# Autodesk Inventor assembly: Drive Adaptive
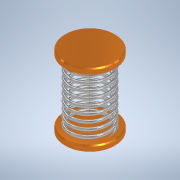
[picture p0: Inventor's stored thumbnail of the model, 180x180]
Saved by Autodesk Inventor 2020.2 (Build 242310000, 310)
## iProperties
Created: 2020-01
Part Number: Drive Adaptive
Document SubType Name: Assembly
Designer: thira
Author: thira
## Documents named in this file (3)
- F:\99.โปรแกรมอัดหน้าจอ\Synergysoft\Adaptive_Spring\Drive Adaptive.iam
- F:\99.โปรแกรมอัดหน้าจอ\Synergysoft\Adaptive_Spring\Plate.ipt
- F:\99.โปรแกรมอัดหน้าจอ\Synergysoft\Adaptive_Spring\Spring_Adaptive.ipt
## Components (3 placed, 2 different names)
1. Plate:1 — Mate:1, Mate:2, Mate:3, Mate:4
2. Spring_Adaptive:1 — Mate:3, Mate:4, Mate:5
3. Plate:2 — Mate:1, Mate:2, Mate:5
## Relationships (5: Mate 5)
- Mate:1: Plate:1 ↔ Plate:2
- Mate:2: Plate:1 ↔ Plate:2
- Mate:3: Plate:1 ↔ Spring_Adaptive:1
- Mate:4: Plate:1 ↔ Spring_Adaptive:1
- Mate:5: Spring_Adaptive:1 ↔ Plate:2
